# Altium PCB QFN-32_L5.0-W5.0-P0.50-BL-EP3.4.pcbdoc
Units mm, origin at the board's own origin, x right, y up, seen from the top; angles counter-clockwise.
Board outline 18.3 x 18.93 mm, 2 copper layers (Top Layer, Bottom Layer), stack 0.07 mm thick; 1 components, 0 nets, 33 pads, 0 vias.
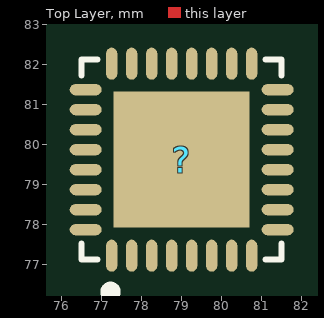
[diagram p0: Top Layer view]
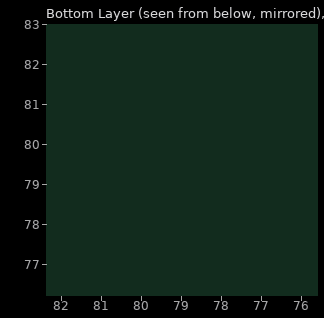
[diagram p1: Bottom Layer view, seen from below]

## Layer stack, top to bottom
Top Solder Mask Layer: solder mask 0.01, Dk 3.3
Top Layer: signal copper 0.035
Bottom Layer: signal copper 0.035
Bottom Solder Mask Layer: solder mask 0.01, Dk 3.3

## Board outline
88.15,69.85 69.85,69.85 69.85,88.779 88.15,88.779

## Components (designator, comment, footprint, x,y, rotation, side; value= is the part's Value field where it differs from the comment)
? "QFN-32_L5.0-W5.0-P0.50-BL-EP3.4" QFN-32_L5.0-W5.0-P0.50-BL-EP3.4 79,79.629 r0 top

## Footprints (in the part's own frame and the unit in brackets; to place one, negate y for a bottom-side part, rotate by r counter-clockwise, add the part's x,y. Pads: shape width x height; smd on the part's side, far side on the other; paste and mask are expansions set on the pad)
QFN-32_L5.0-W5.0-P0.50-BL-EP3.4 [mm]
  oval 0.28x0.8 smd paste+0 mask+0.05: 1(-1.75,-2.4) 2(-1.25,-2.4) 3(-0.75,-2.4) 4(-0.25,-2.4) 5(0.25,-2.4) 6(0.75,-2.4) 7(1.25,-2.4) 8(1.75,-2.4) 17(1.75,2.4) 18(1.25,2.4) 19(0.75,2.4) 20(0.25,2.4) 21(-0.25,2.4) 22(-0.75,2.4) 23(-1.25,2.4) 24(-1.75,2.4)
  oval 0.8x0.28 smd paste+0 mask+0.05: 9(2.4,-1.75) 10(2.4,-1.25) 11(2.4,-0.75) 12(2.4,-0.25) 13(2.4,0.25) 14(2.4,0.75) 15(2.4,1.25) 16(2.4,1.75) 25(-2.4,1.75) 26(-2.4,1.25) 27(-2.4,0.75) 28(-2.4,0.25) 29(-2.4,-0.25) 30(-2.4,-0.75) 31(-2.4,-1.25) 32(-2.4,-1.75)
  rect 3.4x3.4 smd paste+0 mask+0.05: 33(0,0)
  silkscreen extent -2.5,-3.43 2.5,2.5

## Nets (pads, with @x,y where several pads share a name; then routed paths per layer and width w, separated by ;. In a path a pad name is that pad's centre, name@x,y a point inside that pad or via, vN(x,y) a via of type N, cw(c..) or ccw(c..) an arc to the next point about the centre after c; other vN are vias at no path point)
pads on no net: ?.1 ?.2 ?.3 ?.4 ?.5 ?.6 ?.7 ?.8 ?.9 ?.10 ?.11 ?.12 ?.13 ?.14 ?.15 ?.16 ?.17 ?.18 ?.19 ?.20 ?.21 ?.22 ?.23 ?.24 ?.25 ?.26 ?.27 ?.28 ?.29 ?.30 ?.31 ?.32 ?.33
